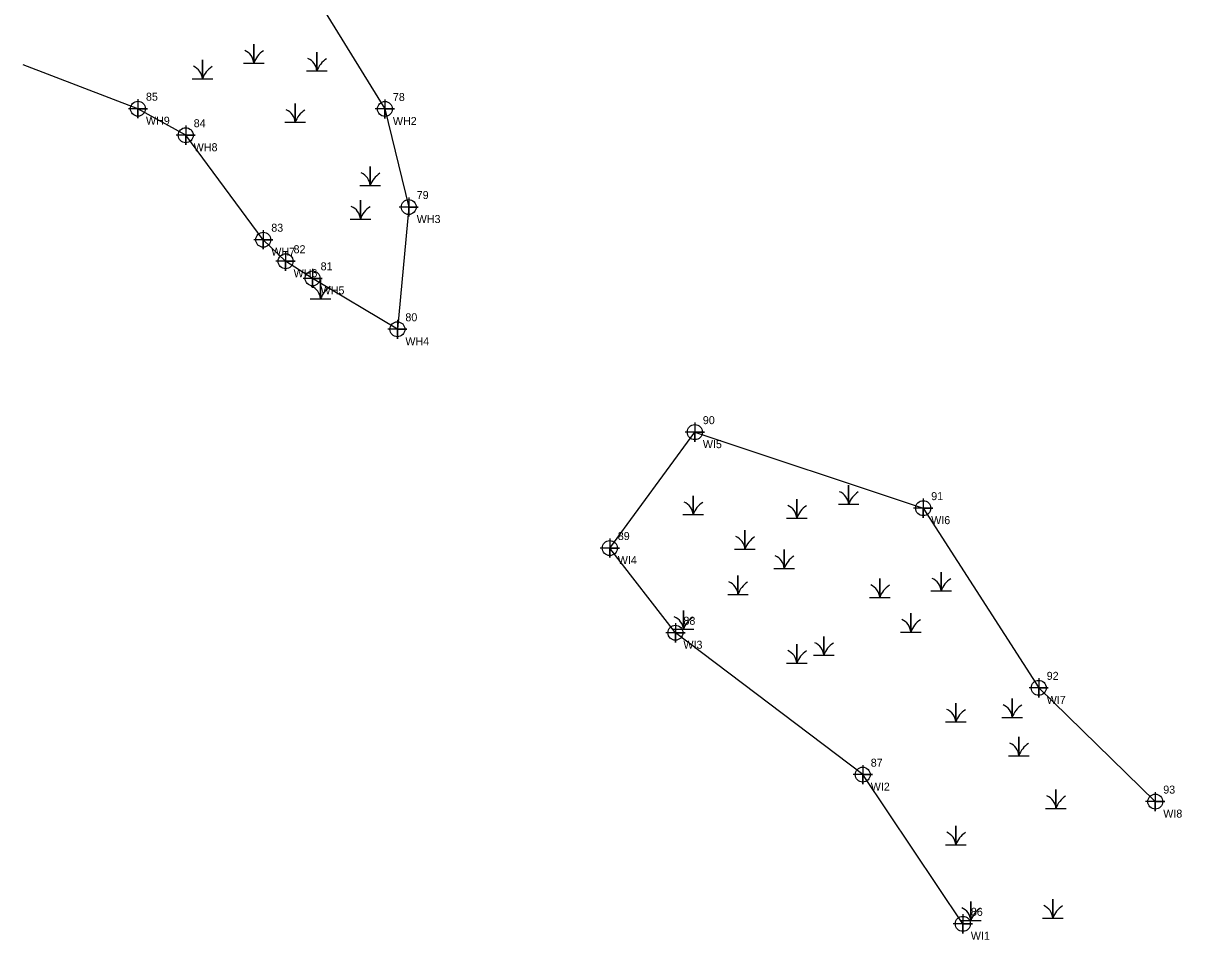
# Model space of a CAD drawing. Extents: x 2189822 to 2191198, y 387253 to 388663.
# Drawn here: x 2189822.3 to 2190184.3, y 387252.9 to 387539.5 of the extents above; entities that cross this region are included whole.
import ezdxf

# ---------------------------------------------------------------- set-up
doc = ezdxf.new("R2010")
doc.units = 0
for name, color, linetype in [('Structure020030_Alleghany', 7, 'Continuous'), ('Structure040008_Ashe', 7, 'Continuous'), ('Structure090007_Brunswick', 7, 'Continuous'), ('Structure620024_Moore', 7, 'Continuous'), ('Structure780124_Rockingham', 7, 'Continuous')]:
    doc.layers.add(name, color=color, linetype=linetype)

msp = doc.modelspace()

# ---------------------------------------------------------------- linework, layer by layer
at = {"layer": 'Structure020030_Alleghany'}
for points in [[(2189858.16, 387515.76), (2189858.16, 387509.76), (2189858.16, 387512.76), (2189861.16, 387512.76), (2189855.16, 387512.76)], [(2189935.31, 387515.67), (2189935.31, 387509.67), (2189935.31, 387512.67), (2189938.31, 387512.67), (2189932.31, 387512.67)], [(2189873.08, 387507.47), (2189873.08, 387501.47), (2189873.08, 387504.47), (2189876.08, 387504.47), (2189870.08, 387504.47)], [(2189942.75, 387485.02), (2189942.75, 387479.02), (2189942.75, 387482.02), (2189945.75, 387482.02), (2189939.75, 387482.02)], [(2189897.31, 387474.8), (2189897.31, 387468.8), (2189897.31, 387471.8), (2189900.31, 387471.8), (2189894.31, 387471.8)], [(2189904.28, 387468.08), (2189904.28, 387462.08), (2189904.28, 387465.08), (2189907.28, 387465.08), (2189901.28, 387465.08)], [(2189912.73, 387462.73), (2189912.73, 387456.73), (2189912.73, 387459.73), (2189915.73, 387459.73), (2189909.73, 387459.73)], [(2189939.21, 387446.81), (2189939.21, 387440.81), (2189939.21, 387443.81), (2189942.21, 387443.81), (2189936.21, 387443.81)], [(2190032.14, 387414.65), (2190032.14, 387408.65), (2190032.14, 387411.65), (2190035.14, 387411.65), (2190029.14, 387411.65)], [(2190103.48, 387390.89), (2190103.48, 387384.89), (2190103.48, 387387.89), (2190106.48, 387387.89), (2190100.48, 387387.89)], [(2190005.57, 387378.42), (2190005.57, 387372.42), (2190005.57, 387375.42), (2190008.57, 387375.42), (2190002.57, 387375.42)], [(2190026.07, 387351.94), (2190026.07, 387345.94), (2190026.07, 387348.94), (2190029.07, 387348.94), (2190023.07, 387348.94)], [(2190139.57, 387334.72), (2190139.57, 387328.72), (2190139.57, 387331.72), (2190142.57, 387331.72), (2190136.57, 387331.72)], [(2190084.6, 387307.58), (2190084.6, 387301.58), (2190084.6, 387304.58), (2190087.6, 387304.58), (2190081.6, 387304.58)], [(2190175.98, 387299.16), (2190175.98, 387293.16), (2190175.98, 387296.16), (2190178.98, 387296.16), (2190172.98, 387296.16)], [(2190115.87, 387260.95), (2190115.87, 387254.95), (2190115.87, 387257.95), (2190118.87, 387257.95), (2190112.87, 387257.95)]]:
    msp.add_lwpolyline(points, dxfattribs=at)
for centre in [(2189858.16, 387512.76), (2189935.31, 387512.67), (2189873.08, 387504.47), (2189942.75, 387482.02), (2189897.31, 387471.8), (2189904.28, 387465.08), (2189912.73, 387459.73), (2189939.21, 387443.81), (2190032.14, 387411.65), (2190103.48, 387387.89), (2190005.57, 387375.42), (2190026.07, 387348.94), (2190139.57, 387331.72), (2190084.6, 387304.58), (2190175.98, 387296.16), (2190115.87, 387257.95)]:
    msp.add_circle(centre, 2.34, dxfattribs=at)
at = {"layer": 'Structure620024_Moore'}
msp.add_line((2189858.16, 387512.76), (2189822.3, 387526.46), dxfattribs=at)
for points in [[(2190072, 387678.13), (2190020.83, 387609.65), (2189984.15, 387558.06), (2189939.6, 387584.08), (2189902.66, 387565.6), (2189935.31, 387512.67), (2189942.75, 387482.02), (2189939.21, 387443.81), (2189912.73, 387459.73), (2189904.28, 387465.08), (2189897.31, 387471.8), (2189873.08, 387504.47), (2189858.16, 387512.76)], [(2190115.87, 387257.95), (2190084.6, 387304.58), (2190026.07, 387348.94), (2190005.57, 387375.42), (2190032.14, 387411.65), (2190103.48, 387387.89), (2190139.57, 387331.72), (2190175.98, 387296.16)]]:
    msp.add_lwpolyline(points, dxfattribs=at)
at = {"layer": 'Structure780124_Rockingham'}
for p, q in [((2189894.34, 387529.69), (2189894.34, 387529.69)), ((2189878.3, 387524.75), (2189878.3, 387524.75)), ((2189914.08, 387527.22), (2189914.08, 387527.22)), ((2189907.29, 387511.17), (2189907.29, 387511.17)), ((2189930.74, 387491.42), (2189930.74, 387491.42)), ((2189927.65, 387480.92), (2189927.65, 387480.92)), ((2189915.23, 387455.98), (2189915.23, 387455.98)), ((2190080.19, 387391.79), (2190080.19, 387391.79)), ((2190031.61, 387388.55), (2190031.61, 387388.55)), ((2190064, 387387.47), (2190064, 387387.47)), ((2190047.8, 387377.75), (2190047.8, 387377.75)), ((2190060.08, 387371.74), (2190060.08, 387371.74)), ((2190045.62, 387363.63), (2190045.62, 387363.63)), ((2190089.91, 387362.62), (2190089.91, 387362.62)), ((2190109.08, 387364.69), (2190109.08, 387364.69)), ((2190028.57, 387352.69), (2190028.57, 387352.69)), ((2190099.62, 387351.82), (2190099.62, 387351.82)), ((2190072.42, 387344.58), (2190072.42, 387344.58)), ((2190064, 387342.1), (2190064, 387342.1)), ((2190113.66, 387323.73), (2190113.66, 387323.73)), ((2190131.29, 387325.18), (2190131.29, 387325.18)), ((2190133.4, 387313.18), (2190133.4, 387313.18)), ((2190144.97, 387296.73), (2190144.97, 387296.73)), ((2190113.66, 387285.32), (2190113.66, 387285.32)), ((2190118.37, 387261.7), (2190118.37, 387261.7)), ((2190143.98, 387262.39), (2190143.98, 387262.39))]:
    msp.add_line(p, q, dxfattribs=at)
for points in [[(2189891.11, 387527.02), (2189894.34, 387527.02), (2189894.34, 387532.93), (2189894.34, 387527.02), (2189897.57, 387527.02)], [(2189910.86, 387524.55), (2189914.08, 387524.55), (2189914.08, 387530.47), (2189914.08, 387524.55), (2189917.31, 387524.55)], [(2189875.07, 387522.08), (2189878.3, 387522.08), (2189878.3, 387528), (2189878.3, 387522.08), (2189881.53, 387522.08)], [(2189904.07, 387508.5), (2189907.3, 387508.5), (2189907.3, 387514.42), (2189907.3, 387508.5), (2189910.52, 387508.5)], [(2189927.51, 387488.74), (2189930.74, 387488.74), (2189930.74, 387494.66), (2189930.74, 387488.74), (2189933.96, 387488.74)], [(2189924.43, 387478.25), (2189927.65, 387478.25), (2189927.65, 387484.17), (2189927.65, 387478.25), (2189930.88, 387478.25)], [(2189912, 387453.3), (2189915.23, 387453.3), (2189915.23, 387459.22), (2189915.23, 387453.3), (2189918.45, 387453.3)], [(2190076.97, 387389.12), (2190080.19, 387389.12), (2190080.19, 387395.04), (2190080.19, 387389.12), (2190083.42, 387389.12)], [(2190028.38, 387385.88), (2190031.61, 387385.88), (2190031.61, 387391.79), (2190031.61, 387385.88), (2190034.84, 387385.88)], [(2190060.77, 387384.8), (2190064, 387384.8), (2190064, 387390.71), (2190064, 387384.8), (2190067.22, 387384.8)], [(2190044.58, 387375.07), (2190047.8, 387375.07), (2190047.8, 387380.99), (2190047.8, 387375.07), (2190051.03, 387375.07)], [(2190056.85, 387369.07), (2190060.08, 387369.07), (2190060.08, 387374.98), (2190060.08, 387369.07), (2190063.3, 387369.07)], [(2190042.4, 387360.95), (2190045.62, 387360.95), (2190045.62, 387366.87), (2190045.62, 387360.95), (2190048.85, 387360.95)], [(2190086.68, 387359.95), (2190089.91, 387359.95), (2190089.91, 387365.87), (2190089.91, 387359.95), (2190093.13, 387359.95)], [(2190105.85, 387362.01), (2190109.08, 387362.01), (2190109.08, 387367.93), (2190109.08, 387362.01), (2190112.3, 387362.01)], [(2190025.34, 387350.02), (2190028.57, 387350.02), (2190028.57, 387355.93), (2190028.57, 387350.02), (2190031.79, 387350.02)], [(2190096.4, 387349.15), (2190099.63, 387349.15), (2190099.63, 387355.06), (2190099.63, 387349.15), (2190102.85, 387349.15)], [(2190069.19, 387341.9), (2190072.42, 387341.9), (2190072.42, 387347.82), (2190072.42, 387341.9), (2190075.64, 387341.9)], [(2190060.77, 387339.42), (2190064, 387339.42), (2190064, 387345.34), (2190064, 387339.42), (2190067.22, 387339.42)], [(2190110.43, 387321.06), (2190113.66, 387321.06), (2190113.66, 387326.98), (2190113.66, 387321.06), (2190116.89, 387321.06)], [(2190128.06, 387322.5), (2190131.29, 387322.5), (2190131.29, 387328.42), (2190131.29, 387322.5), (2190134.51, 387322.5)], [(2190130.18, 387310.51), (2190133.4, 387310.51), (2190133.4, 387316.43), (2190133.4, 387310.51), (2190136.63, 387310.51)], [(2190141.74, 387294.05), (2190144.97, 387294.05), (2190144.97, 387299.97), (2190144.97, 387294.05), (2190148.19, 387294.05)], [(2190110.44, 387282.64), (2190113.66, 387282.64), (2190113.66, 387288.56), (2190113.66, 387282.64), (2190116.89, 387282.64)], [(2190115.14, 387259.02), (2190118.37, 387259.02), (2190118.37, 387264.94), (2190118.37, 387259.02), (2190121.59, 387259.02)], [(2190140.75, 387259.71), (2190143.98, 387259.71), (2190143.98, 387265.63), (2190143.98, 387259.71), (2190147.2, 387259.71)]]:
    msp.add_lwpolyline(points, dxfattribs=at)
for centre, radius, start, end in [((2189889.74, 387526.68), 4.61, 4.1403, 67.535), ((2189901.18, 387524.74), 7.21, 122.1274, 161.6222), ((2189909.48, 387524.21), 4.61, 4.1403, 67.535), ((2189920.92, 387522.27), 7.21, 122.1274, 161.6222), ((2189873.7, 387521.75), 4.61, 4.1403, 67.535), ((2189885.14, 387519.81), 7.21, 122.1274, 161.6222), ((2189902.7, 387508.16), 4.61, 4.1403, 67.535), ((2189914.14, 387506.22), 7.21, 122.1274, 161.6222), ((2189926.14, 387488.41), 4.61, 4.1403, 67.535), ((2189937.58, 387486.47), 7.21, 122.1274, 161.6222), ((2189923.05, 387477.92), 4.61, 4.1403, 67.535), ((2189934.49, 387475.98), 7.21, 122.1274, 161.6222), ((2189910.63, 387452.97), 4.61, 4.1403, 67.535), ((2189922.07, 387451.03), 7.21, 122.1274, 161.6222), ((2190075.59, 387388.78), 4.61, 4.1403, 67.535), ((2190087.03, 387386.84), 7.21, 122.1274, 161.6222), ((2190027.01, 387385.54), 4.61, 4.1403, 67.535), ((2190038.45, 387383.6), 7.21, 122.1274, 161.6222), ((2190059.4, 387384.46), 4.61, 4.1403, 67.535), ((2190070.84, 387382.52), 7.21, 122.1274, 161.6222), ((2190043.2, 387374.74), 4.61, 4.1403, 67.535), ((2190054.65, 387372.8), 7.21, 122.1274, 161.6222), ((2190055.48, 387368.73), 4.61, 4.1403, 67.535), ((2190066.92, 387366.79), 7.21, 122.1274, 161.6222), ((2190104.48, 387361.68), 4.61, 4.1403, 67.535), ((2190115.92, 387359.74), 7.21, 122.1274, 161.6222), ((2190041.02, 387360.62), 4.61, 4.1403, 67.535), ((2190052.47, 387358.68), 7.21, 122.1274, 161.6222), ((2190085.31, 387359.62), 4.61, 4.1403, 67.535), ((2190096.75, 387357.68), 7.21, 122.1274, 161.6222), ((2190023.97, 387349.68), 4.61, 4.1403, 67.535), ((2190035.41, 387347.74), 7.21, 122.1274, 161.6222), ((2190095.03, 387348.81), 4.61, 4.1403, 67.535), ((2190106.47, 387346.87), 7.21, 122.1274, 161.6222), ((2190067.82, 387341.57), 4.61, 4.1403, 67.535), ((2190079.26, 387339.63), 7.21, 122.1274, 161.6222), ((2190059.4, 387339.09), 4.61, 4.1403, 67.535), ((2190070.84, 387337.15), 7.21, 122.1274, 161.6222), ((2190126.69, 387322.17), 4.61, 4.1403, 67.535), ((2190138.13, 387320.23), 7.21, 122.1274, 161.6222), ((2190109.06, 387320.73), 4.61, 4.1403, 67.535), ((2190120.5, 387318.79), 7.21, 122.1274, 161.6222), ((2190128.8, 387310.18), 4.61, 4.1403, 67.535), ((2190140.24, 387308.24), 7.21, 122.1274, 161.6222), ((2190140.37, 387293.72), 4.61, 4.1403, 67.535), ((2190151.81, 387291.78), 7.21, 122.1274, 161.6222), ((2190109.06, 387282.31), 4.61, 4.1403, 67.535), ((2190120.5, 387280.37), 7.21, 122.1274, 161.6222), ((2190113.77, 387258.69), 4.61, 4.1403, 67.535), ((2190125.21, 387256.75), 7.21, 122.1274, 161.6222), ((2190139.38, 387259.38), 4.61, 4.1403, 67.535), ((2190150.82, 387257.44), 7.21, 122.1274, 161.6222)]:
    msp.add_arc(centre, radius, start, end, dxfattribs=at)

# ---------------------------------------------------------------- texts
at = {"layer": 'Structure040008_Ashe'}
for s, p in [('85', (2189860.66, 387515.26)), ('78', (2189937.81, 387515.17)), ('84', (2189875.58, 387506.97)), ('79', (2189945.25, 387484.52)), ('83', (2189899.81, 387474.3)), ('82', (2189906.78, 387467.58)), ('81', (2189915.23, 387462.23)), ('80', (2189941.71, 387446.31)), ('90', (2190034.64, 387414.15)), ('91', (2190105.98, 387390.39)), ('89', (2190008.07, 387377.92)), ('88', (2190028.57, 387351.44)), ('92', (2190142.07, 387334.22)), ('87', (2190087.1, 387307.08)), ('93', (2190178.48, 387298.66)), ('86', (2190118.37, 387260.45))]:
    msp.add_text(s, height=2.5, dxfattribs=at).set_placement(p)
at = {"layer": 'Structure090007_Brunswick'}
for s, p in [('WH9', (2189860.66, 387507.76)), ('WH2', (2189937.81, 387507.67)), ('WH8', (2189875.58, 387499.47)), ('WH3', (2189945.25, 387477.02)), ('WH7', (2189899.81, 387466.8)), ('WH6', (2189906.78, 387460.08)), ('WH5', (2189915.23, 387454.73)), ('WH4', (2189941.71, 387438.81)), ('WI5', (2190034.64, 387406.65)), ('WI6', (2190105.98, 387382.89)), ('WI4', (2190008.07, 387370.42)), ('WI3', (2190028.57, 387343.94)), ('WI7', (2190142.07, 387326.72)), ('WI2', (2190087.1, 387299.58)), ('WI8', (2190178.48, 387291.16)), ('WI1', (2190118.37, 387252.95))]:
    msp.add_text(s, height=2.5, dxfattribs=at).set_placement(p)

doc.saveas('drawing.dxf')
